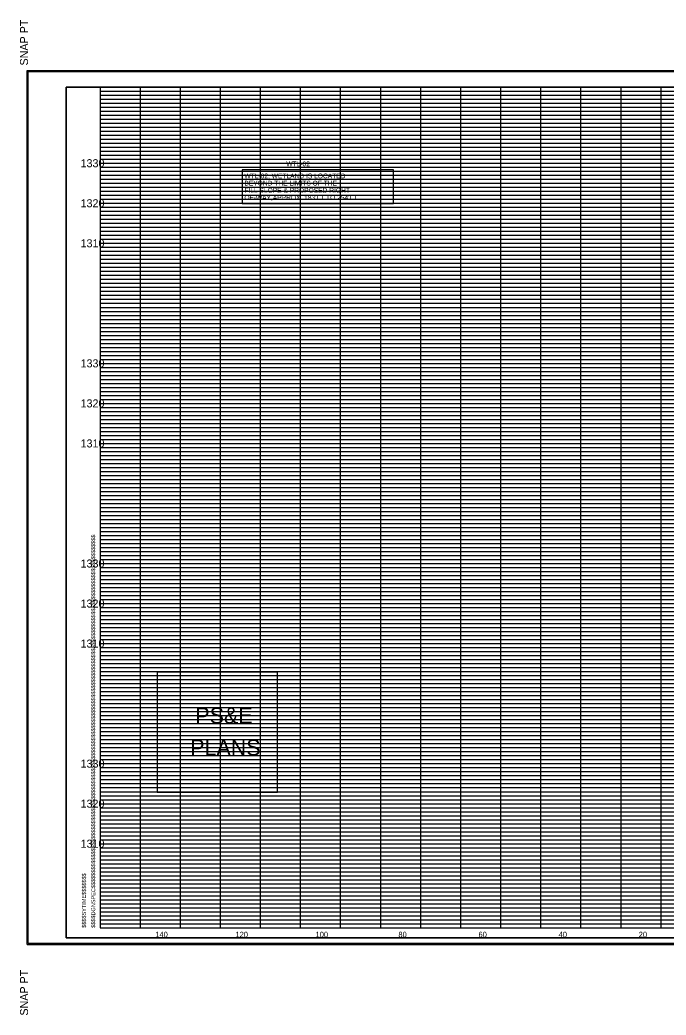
# Model space of a CAD drawing. Extents: x 980 to 1324, y 978 to 1497.
# Drawn here: x 979.9 to 1141.2, y 978.2 to 1226.8 of the extents above; entities that cross this region are included whole.
import ezdxf

# ---------------------------------------------------------------- set-up
doc = ezdxf.new("R2010")
doc.units = 0
for name, color, linetype in [('DESIGN - SHEET - Corner Text', 7, 'Continuous'), ('DESIGN - SHEET - Light Grid', 7, 'Continuous'), ('DESIGN - SHEET - Linework', 7, 'Continuous'), ('DESIGN - SHEET - Plot Shape', 7, 'Continuous'), ('DESIGN - TYPICAL - Finished Grade and Subgrade', 7, 'Continuous'), ('DESIGN - TYPICAL - Text', 7, 'Continuous'), ('SURVEY - NON-TRANSPORTATION - Features', 7, 'Continuous')]:
    doc.layers.add(name, color=color, linetype=linetype)

# ---------------------------------------------------------------- blocks, each defined once
blk = doc.blocks.new('XSTSHT')
at = {"layer": 'DESIGN - SHEET - Light Grid'}
for p, q in [((0, 20.9), (8, 20.9)), ((8, 20.9), (16, 20.9)), ((0, 20.8), (8, 20.8)), ((0, 20.7), (8, 20.7)), ((8, 20.8), (16, 20.8)), ((8, 20.7), (16, 20.7)), ((0, 20.6), (8, 20.6)), ((0, 20.5), (8, 20.5)), ((0, 20.4), (8, 20.4)), ((8, 20.6), (16, 20.6)), ((8, 20.5), (16, 20.5)), ((8, 20.4), (16, 20.4)), ((0, 20.3), (8, 20.3)), ((0, 20.2), (8, 20.2)), ((8, 20.3), (16, 20.3)), ((8, 20.2), (16, 20.2)), ((0, 20.1), (8, 20.1)), ((0, 19.9), (8, 19.9)), ((8, 20.1), (16, 20.1)), ((8, 19.9), (16, 19.9)), ((0, 19.8), (8, 19.8)), ((0, 19.7), (8, 19.7)), ((8, 19.8), (16, 19.8)), ((8, 19.7), (16, 19.7)), ((0, 19.6), (8, 19.6)), ((0, 19.5), (8, 19.5)), ((0, 19.4), (8, 19.4)), ((8, 19.6), (16, 19.6)), ((8, 19.5), (16, 19.5)), ((8, 19.4), (16, 19.4)), ((0, 19.3), (8, 19.3)), ((0, 19.2), (8, 19.2)), ((8, 19.3), (16, 19.3)), ((8, 19.2), (16, 19.2)), ((0, 19.1), (8, 19.1)), ((0, 18.9), (8, 18.9)), ((8, 19.1), (16, 19.1)), ((8, 18.9), (16, 18.9)), ((0, 18.8), (8, 18.8)), ((0, 18.7), (8, 18.7)), ((8, 18.8), (16, 18.8)), ((8, 18.7), (16, 18.7)), ((0, 18.6), (8, 18.6)), ((0, 18.5), (8, 18.5)), ((0, 18.4), (8, 18.4)), ((8, 18.6), (16, 18.6)), ((8, 18.5), (16, 18.5)), ((8, 18.4), (16, 18.4)), ((0, 18.3), (8, 18.3)), ((0, 18.2), (8, 18.2)), ((8, 18.3), (16, 18.3)), ((8, 18.2), (16, 18.2)), ((0, 18.1), (8, 18.1)), ((8, 18.1), (16, 18.1)), ((0, 17.9), (8, 17.9)), ((0, 17.8), (8, 17.8)), ((0, 17.7), (8, 17.7)), ((8, 17.9), (16, 17.9)), ((8, 17.8), (16, 17.8)), ((8, 17.7), (16, 17.7)), ((0, 17.6), (8, 17.6)), ((0, 17.5), (8, 17.5)), ((8, 17.6), (16, 17.6)), ((8, 17.5), (16, 17.5)), ((0, 17.4), (8, 17.4)), ((0, 17.3), (8, 17.3)), ((0, 17.2), (8, 17.2)), ((8, 17.4), (16, 17.4)), ((8, 17.3), (16, 17.3)), ((8, 17.2), (16, 17.2)), ((0, 17.1), (8, 17.1)), ((8, 17.1), (16, 17.1)), ((0, 16.9), (8, 16.9)), ((0, 16.8), (8, 16.8)), ((0, 16.7), (8, 16.7)), ((8, 16.9), (16, 16.9)), ((8, 16.8), (16, 16.8)), ((8, 16.7), (16, 16.7)), ((0, 16.6), (8, 16.6)), ((0, 16.5), (8, 16.5)), ((8, 16.6), (16, 16.6)), ((8, 16.5), (16, 16.5)), ((0, 16.4), (8, 16.4)), ((0, 16.3), (8, 16.3)), ((0, 16.2), (8, 16.2)), ((8, 16.4), (16, 16.4)), ((8, 16.3), (16, 16.3)), ((8, 16.2), (16, 16.2)), ((0, 16.1), (8, 16.1)), ((8, 16.1), (16, 16.1)), ((0, 15.9), (8, 15.9)), ((0, 15.8), (8, 15.8)), ((0, 15.7), (8, 15.7)), ((8, 15.9), (16, 15.9)), ((8, 15.8), (16, 15.8)), ((8, 15.7), (16, 15.7)), ((0, 15.6), (8, 15.6)), ((0, 15.5), (8, 15.5)), ((8, 15.6), (16, 15.6)), ((8, 15.5), (16, 15.5)), ((0, 15.4), (8, 15.4)), ((0, 15.3), (8, 15.3)), ((0, 15.2), (8, 15.2)), ((8, 15.4), (16, 15.4)), ((8, 15.3), (16, 15.3)), ((8, 15.2), (16, 15.2)), ((0, 15.1), (8, 15.1)), ((8, 15.1), (16, 15.1)), ((0, 14.9), (8, 14.9)), ((0, 14.8), (8, 14.8)), ((0, 14.7), (8, 14.7)), ((8, 14.9), (16, 14.9)), ((8, 14.8), (16, 14.8)), ((8, 14.7), (16, 14.7)), ((0, 14.6), (8, 14.6)), ((0, 14.5), (8, 14.5)), ((8, 14.6), (16, 14.6)), ((8, 14.5), (16, 14.5)), ((0, 14.4), (8, 14.4)), ((0, 14.3), (8, 14.3)), ((0, 14.2), (8, 14.2)), ((8, 14.4), (16, 14.4)), ((8, 14.3), (16, 14.3)), ((8, 14.2), (16, 14.2)), ((0, 14.1), (8, 14.1)), ((8, 14.1), (16, 14.1)), ((0, 13.9), (8, 13.9)), ((0, 13.8), (8, 13.8)), ((0, 13.7), (8, 13.7)), ((8, 13.9), (16, 13.9)), ((8, 13.8), (16, 13.8)), ((8, 13.7), (16, 13.7)), ((0, 13.6), (8, 13.6)), ((0, 13.5), (8, 13.5)), ((8, 13.6), (16, 13.6)), ((8, 13.5), (16, 13.5)), ((0, 13.4), (8, 13.4)), ((0, 13.3), (8, 13.3)), ((0, 13.2), (8, 13.2)), ((8, 13.4), (16, 13.4)), ((8, 13.3), (16, 13.3)), ((8, 13.2), (16, 13.2)), ((0, 13.1), (8, 13.1)), ((8, 13.1), (16, 13.1)), ((0, 12.9), (8, 12.9)), ((0, 12.8), (8, 12.8)), ((0, 12.7), (8, 12.7)), ((8, 12.9), (16, 12.9)), ((8, 12.8), (16, 12.8)), ((8, 12.7), (16, 12.7)), ((0, 12.6), (8, 12.6)), ((0, 12.5), (8, 12.5)), ((8, 12.6), (16, 12.6)), ((8, 12.5), (16, 12.5)), ((0, 12.4), (8, 12.4)), ((0, 12.3), (8, 12.3)), ((0, 12.2), (8, 12.2)), ((8, 12.4), (16, 12.4)), ((8, 12.3), (16, 12.3)), ((8, 12.2), (16, 12.2)), ((0, 12.1), (8, 12.1)), ((8, 12.1), (16, 12.1)), ((0, 11.9), (8, 11.9)), ((0, 11.8), (8, 11.8)), ((0, 11.7), (8, 11.7)), ((8, 11.9), (16, 11.9)), ((8, 11.8), (16, 11.8)), ((8, 11.7), (16, 11.7)), ((0, 11.6), (8, 11.6)), ((0, 11.5), (8, 11.5)), ((8, 11.6), (16, 11.6)), ((8, 11.5), (16, 11.5)), ((0, 11.4), (8, 11.4)), ((0, 11.3), (8, 11.3)), ((0, 11.2), (8, 11.2)), ((8, 11.4), (16, 11.4)), ((8, 11.3), (16, 11.3)), ((8, 11.2), (16, 11.2)), ((0, 11.1), (8, 11.1)), ((8, 11.1), (16, 11.1)), ((0, 10.9), (8, 10.9)), ((0, 10.8), (8, 10.8)), ((0, 10.7), (8, 10.7)), ((8, 10.9), (16, 10.9)), ((8, 10.8), (16, 10.8)), ((8, 10.7), (16, 10.7)), ((0, 10.6), (8, 10.6)), ((0, 10.5), (8, 10.5)), ((8, 10.6), (16, 10.6)), ((8, 10.5), (16, 10.5)), ((0, 10.4), (8, 10.4)), ((0, 10.3), (8, 10.3)), ((0, 10.2), (8, 10.2)), ((8, 10.4), (16, 10.4)), ((8, 10.3), (16, 10.3)), ((8, 10.2), (16, 10.2)), ((0, 10.1), (8, 10.1)), ((8, 10.1), (16, 10.1)), ((0, 9.9), (8, 9.9)), ((0, 9.8), (8, 9.8)), ((0, 9.7), (8, 9.7)), ((8, 9.9), (16, 9.9)), ((8, 9.8), (16, 9.8)), ((8, 9.7), (16, 9.7)), ((0, 9.6), (8, 9.6)), ((0, 9.5), (8, 9.5)), ((8, 9.6), (16, 9.6)), ((8, 9.5), (16, 9.5)), ((0, 9.4), (8, 9.4)), ((0, 9.3), (8, 9.3)), ((0, 9.2), (8, 9.2)), ((8, 9.4), (16, 9.4)), ((8, 9.3), (16, 9.3)), ((8, 9.2), (16, 9.2)), ((0, 9.1), (8, 9.1)), ((8, 9.1), (16, 9.1)), ((0, 8.9), (8, 8.9)), ((0, 8.8), (8, 8.8)), ((8, 8.9), (16, 8.9)), ((8, 8.8), (16, 8.8)), ((0, 8.7), (8, 8.7)), ((0, 8.6), (8, 8.6)), ((0, 8.5), (8, 8.5)), ((8, 8.7), (16, 8.7)), ((8, 8.6), (16, 8.6)), ((8, 8.5), (16, 8.5)), ((0, 8.4), (8, 8.4)), ((0, 8.3), (8, 8.3)), ((8, 8.4), (16, 8.4)), ((8, 8.3), (16, 8.3)), ((0, 8.2), (8, 8.2)), ((0, 8.1), (8, 8.1)), ((8, 8.2), (16, 8.2)), ((8, 8.1), (16, 8.1)), ((0, 7.9), (8, 7.9)), ((0, 7.8), (8, 7.8)), ((8, 7.9), (16, 7.9)), ((8, 7.8), (16, 7.8)), ((0, 7.7), (8, 7.7)), ((0, 7.6), (8, 7.6)), ((0, 7.5), (8, 7.5)), ((8, 7.7), (16, 7.7)), ((8, 7.6), (16, 7.6)), ((8, 7.5), (16, 7.5)), ((0, 7.4), (8, 7.4)), ((0, 7.3), (8, 7.3)), ((8, 7.4), (16, 7.4)), ((8, 7.3), (16, 7.3)), ((0, 7.2), (8, 7.2)), ((0, 7.1), (8, 7.1)), ((8, 7.2), (16, 7.2)), ((8, 7.1), (16, 7.1)), ((0, 6.9), (8, 6.9)), ((0, 6.8), (8, 6.8)), ((8, 6.9), (16, 6.9)), ((8, 6.8), (16, 6.8)), ((0, 6.7), (8, 6.7)), ((0, 6.6), (8, 6.6)), ((0, 6.5), (8, 6.5)), ((8, 6.7), (16, 6.7)), ((8, 6.6), (16, 6.6)), ((8, 6.5), (16, 6.5)), ((0, 6.4), (8, 6.4)), ((0, 6.3), (8, 6.3)), ((8, 6.4), (16, 6.4)), ((8, 6.3), (16, 6.3)), ((0, 6.2), (8, 6.2)), ((0, 6.1), (8, 6.1)), ((8, 6.2), (16, 6.2)), ((8, 6.1), (16, 6.1)), ((0, 5.9), (8, 5.9)), ((0, 5.8), (8, 5.8)), ((8, 5.9), (16, 5.9)), ((8, 5.8), (16, 5.8)), ((0, 5.7), (8, 5.7)), ((0, 5.6), (8, 5.6)), ((0, 5.5), (8, 5.5)), ((8, 5.7), (16, 5.7)), ((8, 5.6), (16, 5.6)), ((8, 5.5), (16, 5.5)), ((0, 5.4), (8, 5.4)), ((0, 5.3), (8, 5.3)), ((8, 5.4), (16, 5.4)), ((8, 5.3), (16, 5.3)), ((0, 5.2), (8, 5.2)), ((0, 5.1), (8, 5.1)), ((8, 5.2), (16, 5.2)), ((8, 5.1), (16, 5.1)), ((0, 4.9), (8, 4.9)), ((0, 4.8), (8, 4.8)), ((8, 4.9), (16, 4.9)), ((8, 4.8), (16, 4.8)), ((0, 4.7), (8, 4.7)), ((0, 4.6), (8, 4.6)), ((0, 4.5), (8, 4.5)), ((8, 4.7), (16, 4.7)), ((8, 4.6), (16, 4.6)), ((8, 4.5), (16, 4.5)), ((0, 4.4), (8, 4.4)), ((0, 4.3), (8, 4.3)), ((8, 4.4), (16, 4.4)), ((8, 4.3), (16, 4.3)), ((0, 4.2), (8, 4.2)), ((0, 4.1), (8, 4.1)), ((8, 4.2), (16, 4.2)), ((8, 4.1), (16, 4.1)), ((0, 3.9), (8, 3.9)), ((0, 3.8), (8, 3.8)), ((8, 3.9), (16, 3.9)), ((8, 3.8), (16, 3.8)), ((0, 3.7), (8, 3.7)), ((0, 3.6), (8, 3.6)), ((0, 3.5), (8, 3.5)), ((8, 3.7), (16, 3.7)), ((8, 3.6), (16, 3.6)), ((8, 3.5), (16, 3.5)), ((0, 3.4), (8, 3.4)), ((0, 3.3), (8, 3.3)), ((8, 3.4), (16, 3.4)), ((8, 3.3), (16, 3.3)), ((0, 3.2), (8, 3.2)), ((0, 3.1), (8, 3.1)), ((8, 3.2), (16, 3.2)), ((8, 3.1), (16, 3.1)), ((0, 2.9), (8, 2.9)), ((0, 2.8), (8, 2.8)), ((8, 2.9), (16, 2.9)), ((8, 2.8), (16, 2.8)), ((0, 2.7), (8, 2.7)), ((0, 2.6), (8, 2.6)), ((0, 2.5), (8, 2.5)), ((8, 2.7), (16, 2.7)), ((8, 2.6), (16, 2.6)), ((8, 2.5), (16, 2.5)), ((0, 2.4), (8, 2.4)), ((0, 2.3), (8, 2.3)), ((8, 2.4), (16, 2.4)), ((8, 2.3), (16, 2.3)), ((0, 2.2), (8, 2.2)), ((0, 2.1), (8, 2.1)), ((8, 2.2), (16, 2.2)), ((8, 2.1), (16, 2.1)), ((0, 1.9), (8, 1.9)), ((0, 1.8), (8, 1.8)), ((8, 1.9), (16, 1.9)), ((8, 1.8), (16, 1.8)), ((0, 1.7), (8, 1.7)), ((0, 1.6), (8, 1.6)), ((0, 1.5), (8, 1.5)), ((8, 1.7), (16, 1.7)), ((8, 1.6), (16, 1.6)), ((8, 1.5), (16, 1.5)), ((0, 1.4), (8, 1.4)), ((0, 1.3), (8, 1.3)), ((8, 1.4), (16, 1.4)), ((8, 1.3), (16, 1.3)), ((0, 1.2), (8, 1.2)), ((0, 1.1), (8, 1.1)), ((8, 1.2), (16, 1.2)), ((8, 1.1), (16, 1.1)), ((0, 0.9), (8, 0.9)), ((0, 0.8), (8, 0.8)), ((8, 0.9), (16, 0.9)), ((8, 0.8), (16, 0.8)), ((0, 0.7), (8, 0.7)), ((0, 0.6), (8, 0.6)), ((0, 0.5), (8, 0.5)), ((8, 0.7), (16, 0.7)), ((8, 0.6), (16, 0.6)), ((8, 0.5), (16, 0.5)), ((0, 0.4), (8, 0.4)), ((0, 0.3), (8, 0.3)), ((8, 0.4), (16, 0.4)), ((8, 0.3), (16, 0.3)), ((0, 0.2), (8, 0.2)), ((0, 0.1), (8, 0.1)), ((8, 0.2), (16, 0.2)), ((8, 0.1), (16, 0.1))]:
    blk.add_line(p, q, dxfattribs=at)
at = {"layer": 'DESIGN - SHEET - Linework'}
for p, q in [((-1.823, -0.414), (-1.823, 21.414)), ((-1.823, 21.414), (32.217, 21.414)), ((1, 0), (1, 21)), ((2, 0), (2, 21)), ((3, 0), (3, 21)), ((4, 0), (4, 21)), ((5, 0), (5, 21)), ((6, 0), (6, 21)), ((7, 0), (7, 21)), ((8, 0), (8, 21)), ((9, 0), (9, 21)), ((10, 0), (10, 21)), ((11, 0), (11, 21)), ((12, 0), (12, 21)), ((13, 0), (13, 21)), ((14, 0), (14, 21)), ((0, 20), (28, 20)), ((0, 19), (32, 19)), ((0, 18), (32, 18)), ((0, 17), (32, 17)), ((0, 16), (32, 16)), ((0, 15), (32, 15)), ((0, 14), (32, 14)), ((0, 13), (32, 13)), ((0, 12), (32, 12)), ((0, 11), (32, 11)), ((0, 10), (32, 10)), ((0, 9), (32, 9)), ((0, 8), (32, 8)), ((0, 7), (32, 7)), ((0, 6), (32, 6)), ((0, 5), (32, 5)), ((0, 4), (32, 4)), ((0, 3), (32, 3)), ((0, 2), (32, 2)), ((0, 1), (32, 1)), ((-1.823, -0.414), (32.217, -0.414))]:
    blk.add_line(p, q, dxfattribs=at)
blk.add_lwpolyline([(0, 21), (0, 0), (32, 0), (32, 21), (0, 21)], dxfattribs=at)
at = {"layer": 'DESIGN - SHEET - Plot Shape'}
for points in [[(-1.803, 21.394), (32.197, 21.394), (32.197, -0.394), (-1.803, -0.394)], [(-0.85, 21), (32, 21), (32, -0.25), (-0.85, -0.25)]]:
    blk.add_lwpolyline(points, close=True, dxfattribs=at)
at = {"layer": 'DESIGN - SHEET - Corner Text'}
for s, height, p in [('  SNAP PT', 0.2, (-1.803, 21.394)), ('$$$$DGNSPEC$$$$$$$$$$$$$$$$$$$$$$$$$$$$$$$$$$$$$$$$$$$$$$$$$$$$$$$$$$$$$$$$$$$$$$$$$$$$$$$$$$$$$$$$$$$$$$$$$$$$$$$$$$$$$$$$$$$', 0.100002, (-0.126, 0)), ('$$$$SYTIME$$$$$$$', 0.1, (-0.358, 0)), ('SNAP PT  ', 0.2, (-1.803, -2.194))]:
    blk.add_text(s, height=height, rotation=90, dxfattribs=at).set_placement(p)

msp = doc.modelspace()

# ---------------------------------------------------------------- linework, layer by layer
at = {"layer": 'DESIGN - SHEET - Corner Text'}
msp.add_lwpolyline([(1014.22, 1063.86), (1014.22, 1033.86), (1044.22, 1033.86), (1044.22, 1063.86)], close=True, dxfattribs=at)
at = {"layer": 'DESIGN - SHEET - Plot Shape'}
msp.add_lwpolyline([(991.5, 997.5), (1320, 997.5), (1320, 1210), (991.5, 1210)], close=True, dxfattribs=at)
at = {"layer": 'SURVEY - NON-TRANSPORTATION - Features'}
msp.add_lwpolyline([(1035.42, 1180.97), (1073.23, 1180.97), (1073.23, 1189.39), (1035.42, 1189.39)], close=True, dxfattribs=at)

# ---------------------------------------------------------------- block references
at = {"layer": 'DESIGN - TYPICAL - Finished Grade and Subgrade', "xscale": 10, "yscale": 10}
msp.add_blockref('XSTSHT', (1000, 1000), dxfattribs=at)

# ---------------------------------------------------------------- texts
at = {"layer": 'DESIGN - SHEET - Corner Text'}
for s, p in [('PS&E', (1023.74, 1051.04)), ('PLANS', (1022.46, 1043.04))]:
    msp.add_text(s, height=4, dxfattribs=at).set_placement(p)
at = {"layer": 'DESIGN - TYPICAL - Text'}
for s, height, p in [('     1330     ', 2, (991.37, 1190)), ('     1320     ', 2, (991.37, 1180)), ('     1310     ', 2, (991.37, 1170)), ('     1330     ', 2, (991.37, 1140)), ('     1320     ', 2, (991.37, 1130)), ('     1310     ', 2, (991.37, 1120)), ('     1330     ', 2, (991.37, 1090)), ('     1320     ', 2, (991.37, 1080)), ('     1310     ', 2, (991.37, 1070)), ('     1330     ', 2, (991.37, 1040)), ('     1320     ', 2, (991.37, 1030)), ('     1310     ', 2, (991.37, 1020)), ('     140     ', 1.4, (1011.14, 997.6)), ('     120     ', 1.4, (1031.14, 997.6)), ('     100     ', 1.4, (1051.14, 997.6)), ('     80     ', 1.4, (1071.82, 997.6)), ('     60     ', 1.4, (1091.82, 997.6)), ('     40     ', 1.4, (1111.82, 997.6)), ('     20     ', 1.4, (1131.82, 997.6))]:
    msp.add_text(s, height=height, dxfattribs=at).set_placement(p)
at = {"layer": 'SURVEY - NON-TRANSPORTATION - Features'}
for s, p in [('WTL-02', (1046.44, 1190.24)), ('WTL-02, WETLAND IS LOCATED ', (1035.98, 1187.23)), ('BEYOND THE LIMITS OF THE ', (1035.98, 1185.43)), ('FILL SLOPE & PROPOSED RIGHT-', (1035.98, 1183.63)), ("OF-WAY,APPROX. 183'LT.TO 254'LT.", (1035.98, 1181.83))]:
    msp.add_text(s, height=1.2, dxfattribs=at).set_placement(p)

doc.saveas('drawing.dxf')
